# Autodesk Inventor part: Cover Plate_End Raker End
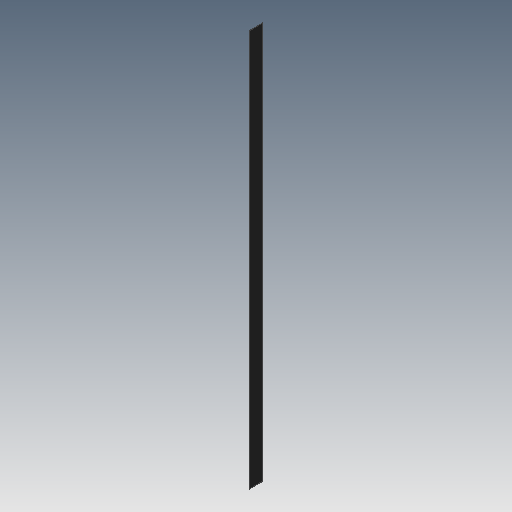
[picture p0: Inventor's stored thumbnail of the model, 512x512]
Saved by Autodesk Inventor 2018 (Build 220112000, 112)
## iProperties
Created: 2018-02
Part Number: Cover Plate_End Raker End
Material: Steel, Mild
Document SubType Name: Sheet Metal
Designer: STK
Density: 7.85 g/cm^3
Sheet Metal Rule: Default
Appearance: Rubber - Black
Author: STK
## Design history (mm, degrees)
node "Face1"
  sketch "Sketch1"
    geometry: L1 (5816.6, 196.85)-(-5816.6, 196.85); L2 (-5816.6, 196.85)-(-5816.6, -196.85); L3 (-5816.6, -196.85)-(5816.6, -196.85); L4 (5816.6, -196.85)-(5816.6, 196.85); L5 (5816.6, 196.85)-(-5816.6, -196.85); L6 (-5816.6, 196.85)-(5816.6, -196.85); 1 further point
    constraints: 12 end point, 2 midpoint, 2 parallel, 1 horizontal, 1 perpendicular
    dimensions: "d0" = 393.7 distance of L3.end L1.start; "d1" = 11633.2 distance of L2.end L3.end
body "Solid1"
face "Plate1" dims "d2" = 6.35 (= Thickness)
other parameters: "Thickness" = 6.35 (derived), "KFactor" = 4.4, "BendRadius" = 6.35 (= Thickness), "BendReliefWidth" = 6.35 (= Thickness), "BendReliefDepth" = 3.175 (= 0.5 x Thickness), "CornerReliefSize" = 25.4 (= 4 x Thickness), "SeamGap" = 0.00508, "MinimumRemnant" = 12.7 (= 2 x Thickness), "TransitionRadius" = 6.35 (= BendRadius), "JacobiRadiusSize" = 6.35 (= BendRadius), "GapSize" = 6.35 (= Thickness)
